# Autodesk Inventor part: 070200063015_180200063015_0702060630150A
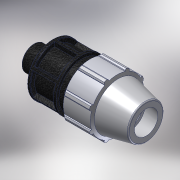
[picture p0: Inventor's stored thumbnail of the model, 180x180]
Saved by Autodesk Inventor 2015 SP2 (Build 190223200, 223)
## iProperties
Created: 2017-02
Part Number: 070200063015_180200063015_0702060630150A
Material: PVC-Piping
Description: PLASSON MALE ADAPTOR 63-1.1/2"
Document SubType Name: Modeling
Designer: KIM
Mass: 92.6774 g
Surface Area: 199.44 cm^2
Volume: 66.1981 cm^3
Density: 1.4 g/cm^3
Appearance: PTFE
Author: KIM
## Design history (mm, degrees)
derived "07020.ipt"
feature "Solid1::07020.ipt"
tag "TaggingFeature1"
body "Solid1"
other parameters: "d2" = 63, "d4" = 22, "d5" = 38.5, "d7" = 113, "d8" = 84.75, "d9" = 22, "d11" = 4.4, "d12" = 90.4, "d13" = 120 deg, "d14" = 88.2, "d15" = 6 deg, "d16" = 101.7, "d18" = 3.15, "d19" = 35 deg, "d20" = 17.5 deg, "d21" = 105.09, "d23" = 0, "d25" = 360 deg, "d27" = 2.26, "d34" = 5.65, "d36" = 0, "d42" = 38.5, "d43" = 3.39, "d46" = 1.89, "d49" = 123, "d51" = 154, "d52" = 22, "d53" = 1.26, "d55" = 360 deg, "d57" = 47.803, "d58" = 33.4621, "d59" = 30.8, "d_" = 63, "E_" = 113, "H_" = 154, "l_" = 123, "l_2" = 22, "R_" = 47.803
